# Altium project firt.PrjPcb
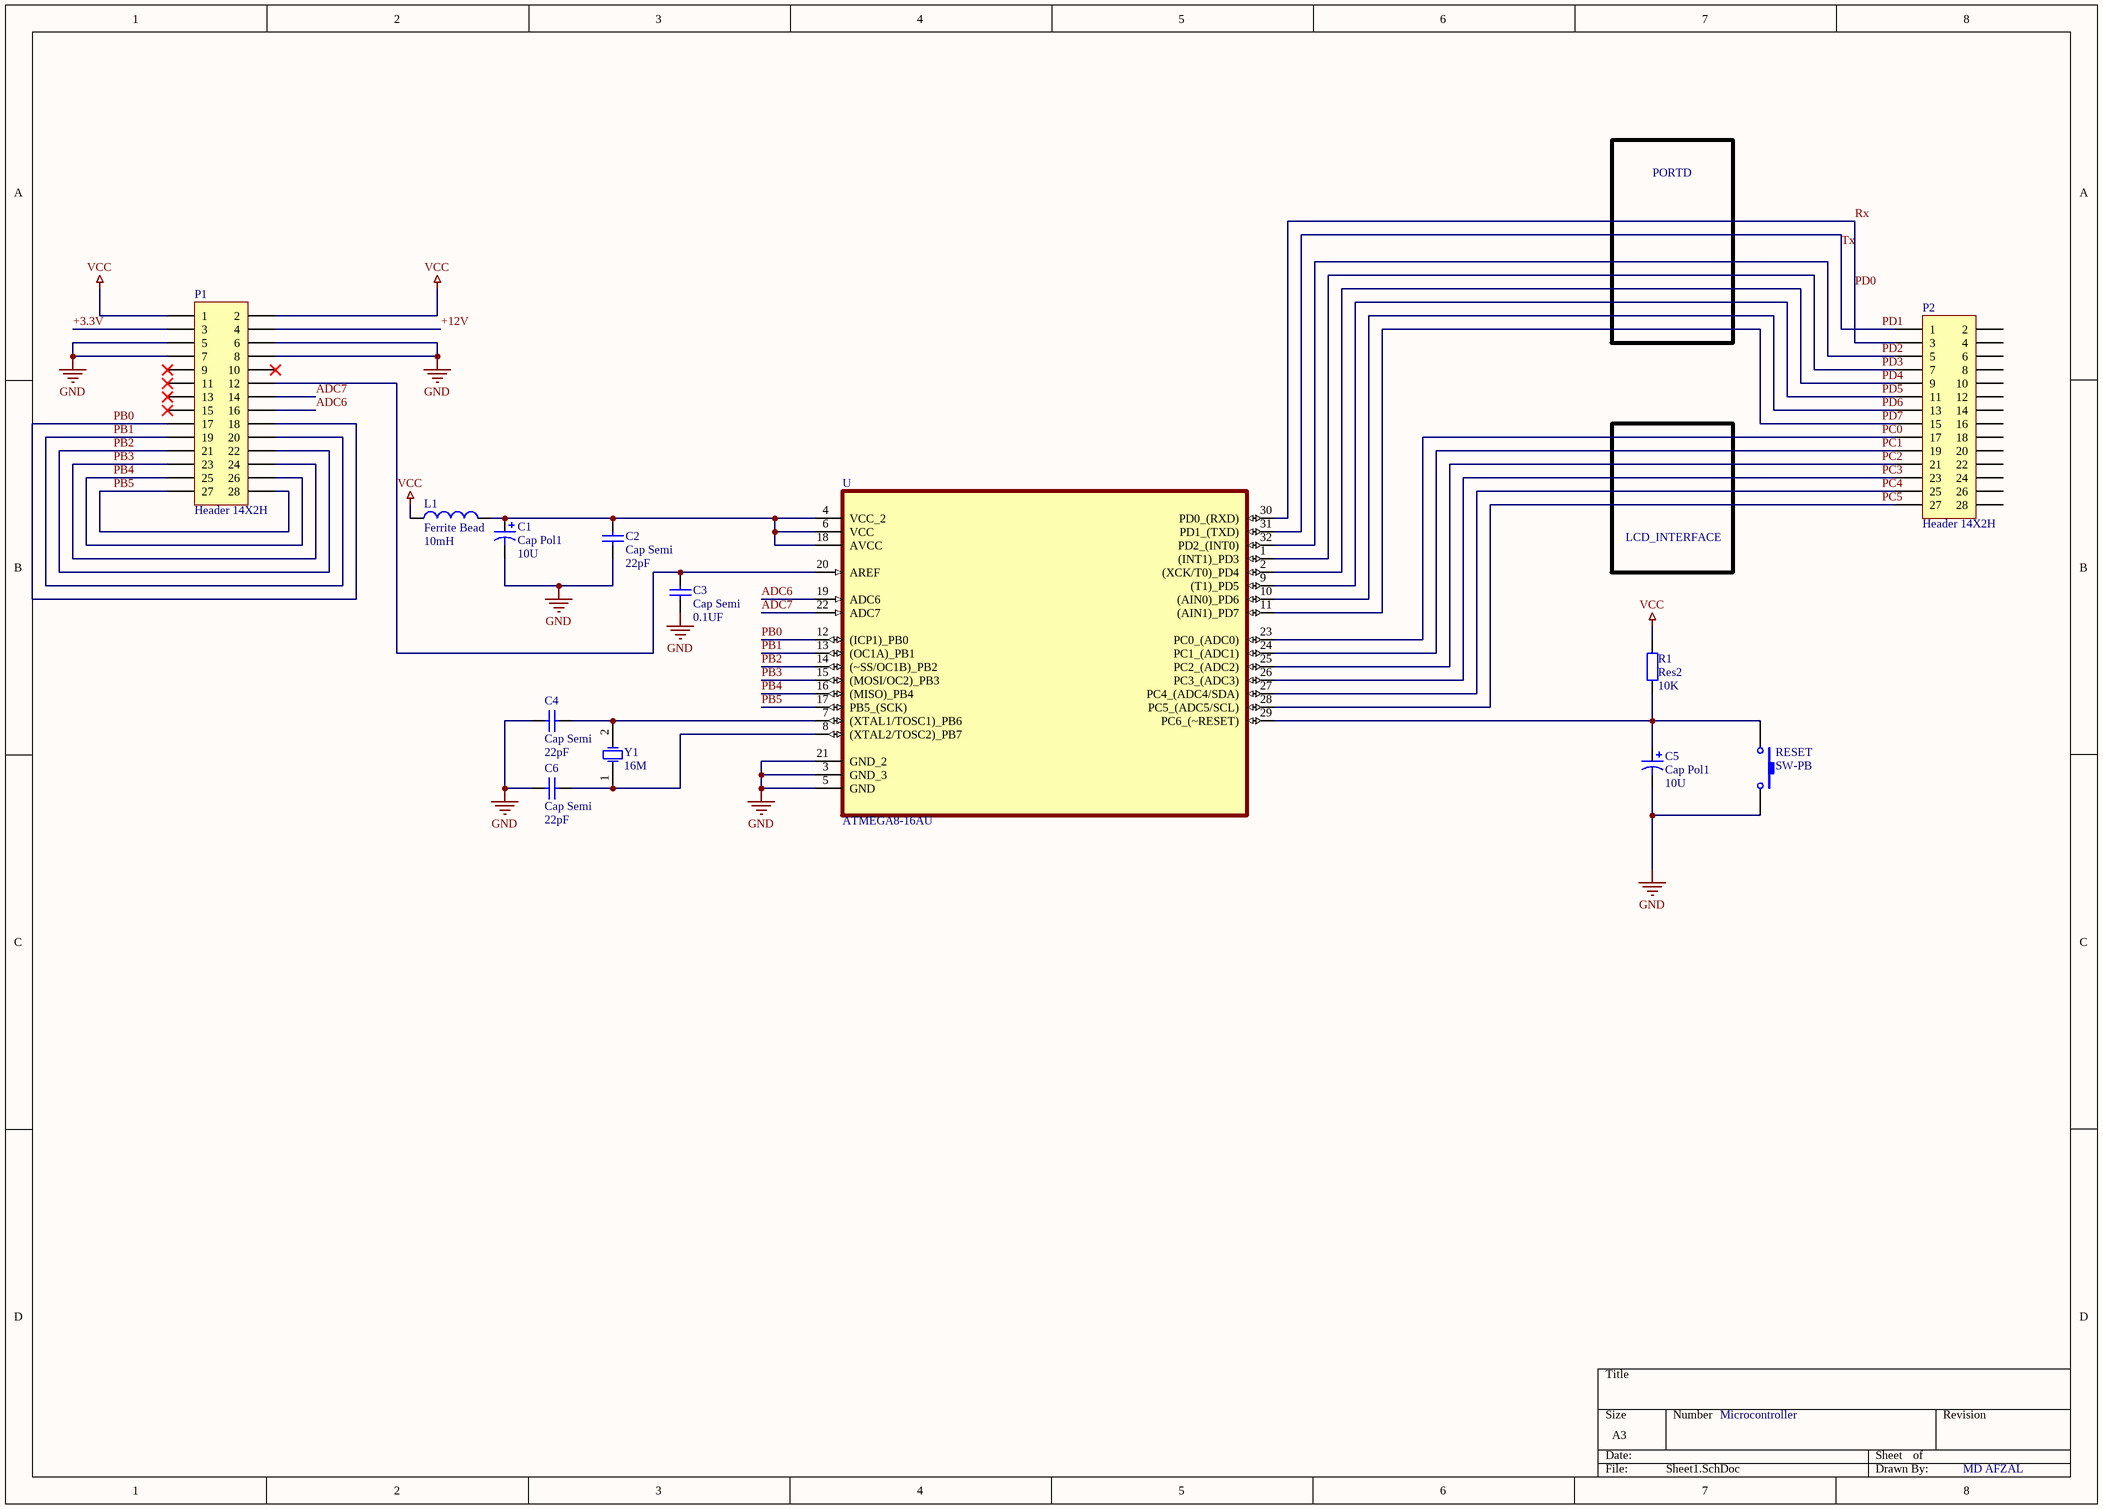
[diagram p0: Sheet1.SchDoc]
1 sheet, 13 parts. Net scope: global (net labels, ports and power ports of the same name join across sheets).
Board file: PCB1.PcbDoc

## Sheet Sheet1.SchDoc
size A3

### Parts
C1  Cap Pol1  value 10U  [CAP_EEV-FK0J332V]
C2  Cap Semi  value 22pF  [C1206]
C3  Cap Semi  value 0.1UF  [C1206]
C4  Cap Semi  value 22pF  [C1206]
C5  Cap Pol1  value 10U  [CAP_EEV-FK0J332V]
C6  Cap Semi  value 22pF  [C1206]
L1  Ferrite Bead  value 10mH  [0402-A]
P1  Header 14X2H  [HEADER]
P2  Header 14X2H  [HEADER]
R1  Res2  value 10K  [AXIAL-0.4]
RESET  SW-PB  [SPST-2]
U  ATMEGA8-16AU  [QFP80P900X900X120-32N]
Y1  16M  [R38]

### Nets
GND: C1.2 C2.1 C3.1 C4.1 C5.2 C6.1 P1.5 P1.6 P1.7 P1.8 RESET.2 U.3(GND_3) U.5(GND) U.21(GND_2)
VCC: L1.1 P1.1 P1.2 R1.2
+3.3V: P1.3
+12V: P1.4
ADC6: P1.16 U.19(ADC6)
ADC7: P1.14 U.22(ADC7)
PB0: P1.17 P1.18 U.12((ICP1)_PB0)
PB1: P1.19 P1.20 U.13((OC1A)_PB1)
PB2: P1.21 P1.22 U.14((~SS/OC1B)_PB2)
PB3: P1.23 P1.24 U.15((MOSI/OC2)_PB3)
PB4: P1.25 P1.26 U.16((MISO)_PB4)
PB5: P1.27 P1.28 U.17(PB5_(SCK))
PC0: P2.17 U.23(PC0_(ADC0))
PC1: P2.19 U.24(PC1_(ADC1))
PC2: P2.21 U.25(PC2_(ADC2))
PC3: P2.23 U.26(PC3_(ADC3))
PC4: P2.25 U.27(PC4_(ADC4/SDA))
PC5: P2.27 U.28(PC5_(ADC5/SCL))
PD0: P2.3 U.30(PD0_(RXD))  [also labelled Rx]
PD1: P2.1 U.31(PD1_(TXD))  [also labelled Tx]
PD2: P2.5 U.32(PD2_(INT0))
PD3: P2.7 U.1((INT1)_PD3)
PD4: P2.9 U.2((XCK/T0)_PD4)
PD5: P2.11 U.9((T1)_PD5)
PD6: P2.13 U.10((AIN0)_PD6)
PD7: P2.15 U.11((AIN1)_PD7)
NetC1_1: C1.1 C2.2 L1.2 U.4(VCC_2) U.6(VCC) U.18(AVCC)
NetC3_2: C3.2 P1.12 U.20(AREF)
NetC4_2: C4.2 U.7((XTAL1/TOSC1)_PB6) Y1.2(OSC2)
NetC5_1: C5.1 R1.1 RESET.1 U.29(PC6_(~RESET))
NetC6_2: C6.2 U.8((XTAL2/TOSC2)_PB7) Y1.1(OSC1)

Not connected (* = marked no-connect by the designer): P1 9* 10* 11* 13* 15*; P2 2 4 6 8 10 12 14 16 18 20 22 24 26 28

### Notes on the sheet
- PORTD
- LCD_INTERFACE
- Microcontroller
- MD AFZAL

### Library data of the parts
C1 C5 = Cap Pol1: Polarized Capacitor (Radial)
C2-C4 C6 = Cap Semi: Capacitor (Semiconductor SIM Model)
L1 = Inductor: Code_IEC: 1005
P1 P2 = Header 14X2H: Header, 14-Pin, Dual row, Right Angle
R1 = Res2: Resistor
RESET = SW-PB: Switch
U = ATMEGA8-16AU: AVR AVRÂ® ATmega Microcontroller IC 8-Bit 16MHz 8KB _4K x 16_ FLASH 32-TQFP _7x7_; MF: Microchip Technology
Y1 = XTAL: Crystal Oscillator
